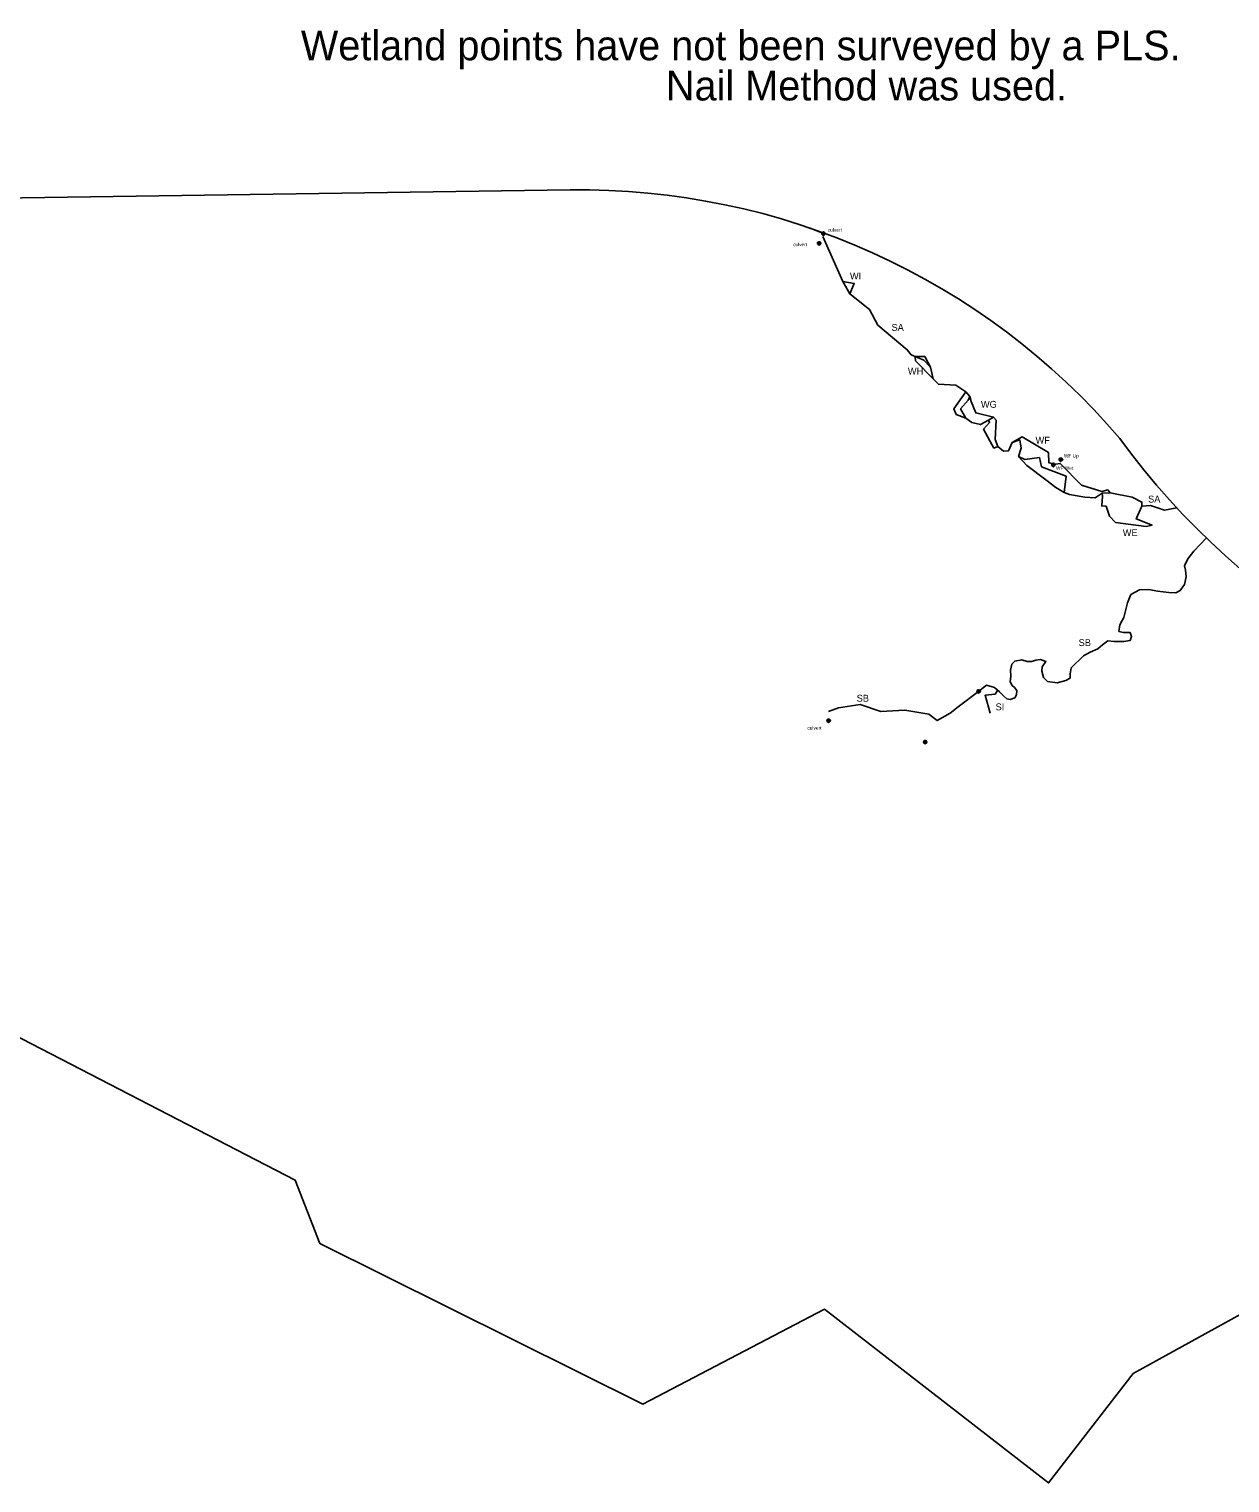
# Model space of a CAD drawing. Extents: x 1637473 to 1644249, y 841388 to 844031.
# Drawn here: x 1640861 to 1642597, y 841388 to 843491 of the extents above; entities that cross this region are included whole.
import ezdxf

# ---------------------------------------------------------------- set-up
doc = ezdxf.new("R2010")
doc.units = 0
for name, color, linetype in [('Default', 7, 'Continuous'), ('Default Symbol CELL', 7, 'Continuous'), ('Exist Environmental Wetland Boundary', 7, 'Continuous'), ('Exist Environmental Wetland Boundary Text', 7, 'Continuous'), ('Exist Hydro Jurisdictional Stream or Body of Water Mitigable', 7, 'Continuous'), ('Exist Hydro Jurisdictional Stream or Body of Water Mitigable Cogo Point CELL', 7, 'Continuous')]:
    doc.layers.add(name, color=color, linetype=linetype)

msp = doc.modelspace()

# ---------------------------------------------------------------- linework, layer by layer
at = {"layer": 'Default'}
for points in [[(1640783.8, 843245.6), (1641643, 843258.2), (1641671.1, 843258.2), (1641699.3, 843257.5), (1641727.4, 843256), (1641755.5, 843253.7), (1641783.4, 843250.6), (1641811.3, 843246.8), (1641839.1, 843242.2), (1641866.8, 843236.8), (1641894.3, 843230.7), (1641921.6, 843223.9), (1641948.7, 843216.3), (1641975.6, 843207.9), (1642002.2, 843198.8), (1642028.6, 843189), (1642054.7, 843178.5), (1642080.5, 843167.3), (1642106, 843155.3), (1642131.2, 843142.7), (1642156, 843129.3), (1642180.4, 843115.3), (1642204.5, 843100.7), (1642228.1, 843085.3), (1642251.3, 843069.4), (1642274, 843052.8), (1642296.3, 843035.6), (1642318.1, 843017.8), (1642339.4, 842999.3), (1642360.2, 842980.4), (1642380.5, 842960.8), (1642400.2, 842940.7), (1642419.4, 842920.1), (1642437.9, 842898.9), (1642455, 842876), (1642472.7, 842853.5), (1642491, 842831.5), (1642509.8, 842810), (1642529.2, 842789), (1642549.2, 842768.6), (1642569.7, 842748.7), (1642590.7, 842729.3), (1642612.2, 842710.5)], [(1644050.4, 841886.8), (1643207.5, 841960.4), (1642457.5, 841546.6), (1642335, 841388.5), (1642010.8, 841639.7), (1641748.4, 841502.2), (1641281.1, 841734.9), (1641245.4, 841826.3), (1640567.4, 842176.5)]]:
    msp.add_lwpolyline(points, dxfattribs=at)
at = {"layer": 'Default Symbol CELL'}
for points in [[(1642341.8, 842863.8), (1642341.8, 842857.8), (1642341.8, 842860.8), (1642344.8, 842860.8), (1642338.8, 842860.8)], [(1642352.6, 842871.4), (1642352.6, 842865.4), (1642352.6, 842868.4), (1642355.6, 842868.4), (1642349.6, 842868.4)]]:
    msp.add_lwpolyline(points, dxfattribs=at)
for centre in [(1642352.6, 842868.4), (1642341.8, 842860.8)]:
    msp.add_circle(centre, 2.34, dxfattribs=at)
at = {"layer": 'Exist Environmental Wetland Boundary'}
for points in [[(1642037.7, 843125.7), (1642053.9, 843122.9), (1642047.4, 843108.2)], [(1642156.1, 843017.2), (1642164.1, 843001.8), (1642168.1, 842985.2), (1642142.6, 843011.3), (1642142, 843017.4)], [(1642215.1, 842966.4), (1642221, 842959.7), (1642222.8, 842952.2), (1642229.7, 842935.8), (1642255.5, 842929.7), (1642259.4, 842925.1), (1642257.9, 842897.2), (1642261.5, 842887), (1642255.9, 842884.8), (1642240.9, 842912.2), (1642249.7, 842922), (1642248.3, 842925.2), (1642236.5, 842919), (1642223.9, 842921.9), (1642215.3, 842928.2), (1642201.4, 842933.7), (1642198.1, 842941.9)], [(1642282.4, 842893.1), (1642297, 842901.1), (1642334.6, 842878.7), (1642335.5, 842863.4), (1642345.4, 842861.9), (1642351.8, 842862.6), (1642382.5, 842831.1), (1642411.9, 842822.3), (1642420.6, 842824.4), (1642423.9, 842820.4), (1642412.5, 842819.5), (1642402.2, 842812.8), (1642387.3, 842814), (1642365.3, 842817.8), (1642357.3, 842820.5), (1642345.3, 842827.9), (1642331, 842838.8), (1642303.5, 842859.7), (1642291.5, 842872.8), (1642295.4, 842884.8), (1642293.5, 842896.8)], [(1642412.5, 842819.5), (1642423.9, 842820.4), (1642455.6, 842814.1), (1642469.9, 842806.8), (1642470, 842800.9), (1642461.6, 842782.5), (1642484.7, 842773.6), (1642476, 842771.5), (1642431.8, 842777.2), (1642423.2, 842786.4), (1642418.2, 842800.8), (1642411.8, 842801.4), (1642412.7, 842815.5)]]:
    msp.add_lwpolyline(points, close=True, dxfattribs=at)
at = {"layer": 'Exist Hydro Jurisdictional Stream or Body of Water Mitigable'}
msp.add_line((1641989.4, 843203.2), (1642009.3, 843195.1), dxfattribs=at)
for points in [[(1642008.6, 843190.9), (1642037.7, 843125.7), (1642053.9, 843122.9), (1642047.4, 843108.2), (1642075.9, 843085.4), (1642088, 843062.9), (1642130.6, 843027), (1642136.3, 843019.8), (1642154.6, 843012), (1642164.1, 843001.8), (1642168.1, 842985.2), (1642175.6, 842977.3), (1642200.8, 842975.8), (1642215.1, 842966.4), (1642221, 842959.7), (1642218.5, 842954), (1642207.7, 842941.9), (1642215.3, 842928.2), (1642223.9, 842921.9), (1642236.5, 842919), (1642248.3, 842925.2), (1642255.5, 842929.7), (1642259.4, 842925.1), (1642257.9, 842897.1), (1642261.5, 842887), (1642269.8, 842880.6), (1642277.2, 842881), (1642282.4, 842893.1), (1642293.5, 842896.8), (1642295.4, 842884.8), (1642291.5, 842872.8), (1642300.6, 842868.2), (1642321.6, 842871.1), (1642324.5, 842858), (1642360.3, 842844.4), (1642357.3, 842820.5), (1642365.3, 842817.8), (1642387.3, 842814), (1642402.2, 842812.8), (1642412.5, 842819.5), (1642423.9, 842820.4), (1642455.6, 842814.1), (1642469.9, 842806.8), (1642470, 842800.9), (1642482.4, 842801.8), (1642502.4, 842795), (1642520.5, 842798.5)], [(1642016.7, 842504), (1642031.1, 842509.3), (1642062.6, 842514.3), (1642092.2, 842504.2), (1642127.3, 842506.1), (1642161.7, 842500), (1642174, 842490.8), (1642192.5, 842501.7), (1642204.2, 842510.6), (1642233.7, 842533.1), (1642245.1, 842542.3), (1642257, 842538.5), (1642263.8, 842532.3), (1642270.3, 842526.1), (1642274.4, 842522.5), (1642279.5, 842521.4), (1642286.1, 842523.6), (1642288.4, 842528.2), (1642289.1, 842534.4), (1642285.8, 842538.5), (1642282.2, 842541.7), (1642279.5, 842546.7), (1642280.3, 842554.9), (1642280, 842563.7), (1642281.6, 842572.3), (1642286, 842577), (1642296.1, 842578.6), (1642304.2, 842576.5), (1642310.9, 842576.4), (1642316.6, 842578.4), (1642323.5, 842579), (1642331, 842576.2), (1642325.5, 842568.6), (1642325, 842562.5), (1642327.8, 842553.4), (1642333.6, 842547.6), (1642347.4, 842545.6), (1642359.8, 842548.6), (1642366.2, 842552.3), (1642366.2, 842558.7), (1642367.4, 842567), (1642385.4, 842584.5), (1642395.3, 842589.8), (1642406, 842594.8), (1642413.1, 842600.5), (1642420.6, 842606.4), (1642429.7, 842605.2), (1642443.3, 842605), (1642452.7, 842606.8), (1642455, 842612.4), (1642452.8, 842618.2), (1642443.5, 842618.3), (1642436.7, 842619.7), (1642437.8, 842629.2), (1642443.6, 842639.9), (1642449.3, 842661), (1642453.8, 842673), (1642466.6, 842680.1), (1642480, 842680.3), (1642492.4, 842678.1), (1642508.6, 842676.1), (1642519, 842675.6), (1642525.4, 842678.8), (1642531.6, 842687.8), (1642534, 842698.5), (1642533, 842708.3), (1642531.4, 842714.8), (1642536.3, 842724.9), (1642545.1, 842735.7), (1642563.3, 842754.9)], [(1642261.2, 842534.6), (1642257.6, 842529.3), (1642243.1, 842527.5), (1642250.6, 842501.6)], [(1642250.6, 842501.6), (1642243.1, 842527.5), (1642257.6, 842529.3)]]:
    msp.add_lwpolyline(points, dxfattribs=at)
at = {"layer": 'Exist Hydro Jurisdictional Stream or Body of Water Mitigable Cogo Point CELL'}
for points in [[(1642003.1, 843184), (1642003.1, 843178), (1642003.1, 843181), (1642006.1, 843181), (1642000.1, 843181)], [(1642009.3, 843198.1), (1642009.3, 843192.1), (1642009.3, 843195.1), (1642012.3, 843195.1), (1642006.3, 843195.1)], [(1642233.7, 842536.1), (1642233.7, 842530.1), (1642233.7, 842533.1), (1642236.7, 842533.1), (1642230.7, 842533.1)], [(1642016.9, 842493.8), (1642016.9, 842487.8), (1642016.9, 842490.8), (1642019.9, 842490.8), (1642013.9, 842490.8)], [(1642156.4, 842462.9), (1642156.4, 842456.9), (1642156.4, 842459.9), (1642159.4, 842459.9), (1642153.4, 842459.9)]]:
    msp.add_lwpolyline(points, dxfattribs=at)
for centre in [(1642003.1, 843181), (1642009.3, 843195.1), (1642233.7, 842533.1), (1642016.9, 842490.8), (1642156.4, 842459.9)]:
    msp.add_circle(centre, 2.34, dxfattribs=at)

# ---------------------------------------------------------------- texts
at = {"layer": 'Default'}
for s, height, p in [('Wetland points have not been surveyed by a PLS.', 42.885, (1641253.8, 843445.7)), ('Nail Method was used. ', 42.885, (1641781.6, 843387.6)), ('WF Up', 5, (1642357.1, 842871.3)), ('WF Wet', 5, (1642345.7, 842853.5))]:
    msp.add_text(s, height=height, dxfattribs=at).set_placement(p)
at = {"layer": 'Exist Environmental Wetland Boundary Text'}
for s, height, p in [('culvert', 5, (1642015.7, 843197.8)), ('culvert', 5, (1641965.5, 843176.9)), ('WI', 10, (1642047.7, 843128.7)), ('SA', 10, (1642107.8, 843054.4)), ('WH', 10, (1642131.5, 842991.3)), ('WG', 10, (1642237.1, 842943.2)), ('WF', 10, (1642316.1, 842891.3)), ('SA', 10, (1642478.8, 842806.2)), ('WE', 10, (1642442.2, 842757.6)), ('SB', 10, (1642378.4, 842598.6)), ('SB', 10, (1642057.4, 842518.2)), ('SI', 10, (1642258.3, 842505.7)), ('culvert', 5, (1641986.2, 842477.8))]:
    msp.add_text(s, height=height, dxfattribs=at).set_placement(p)

doc.saveas('drawing.dxf')
